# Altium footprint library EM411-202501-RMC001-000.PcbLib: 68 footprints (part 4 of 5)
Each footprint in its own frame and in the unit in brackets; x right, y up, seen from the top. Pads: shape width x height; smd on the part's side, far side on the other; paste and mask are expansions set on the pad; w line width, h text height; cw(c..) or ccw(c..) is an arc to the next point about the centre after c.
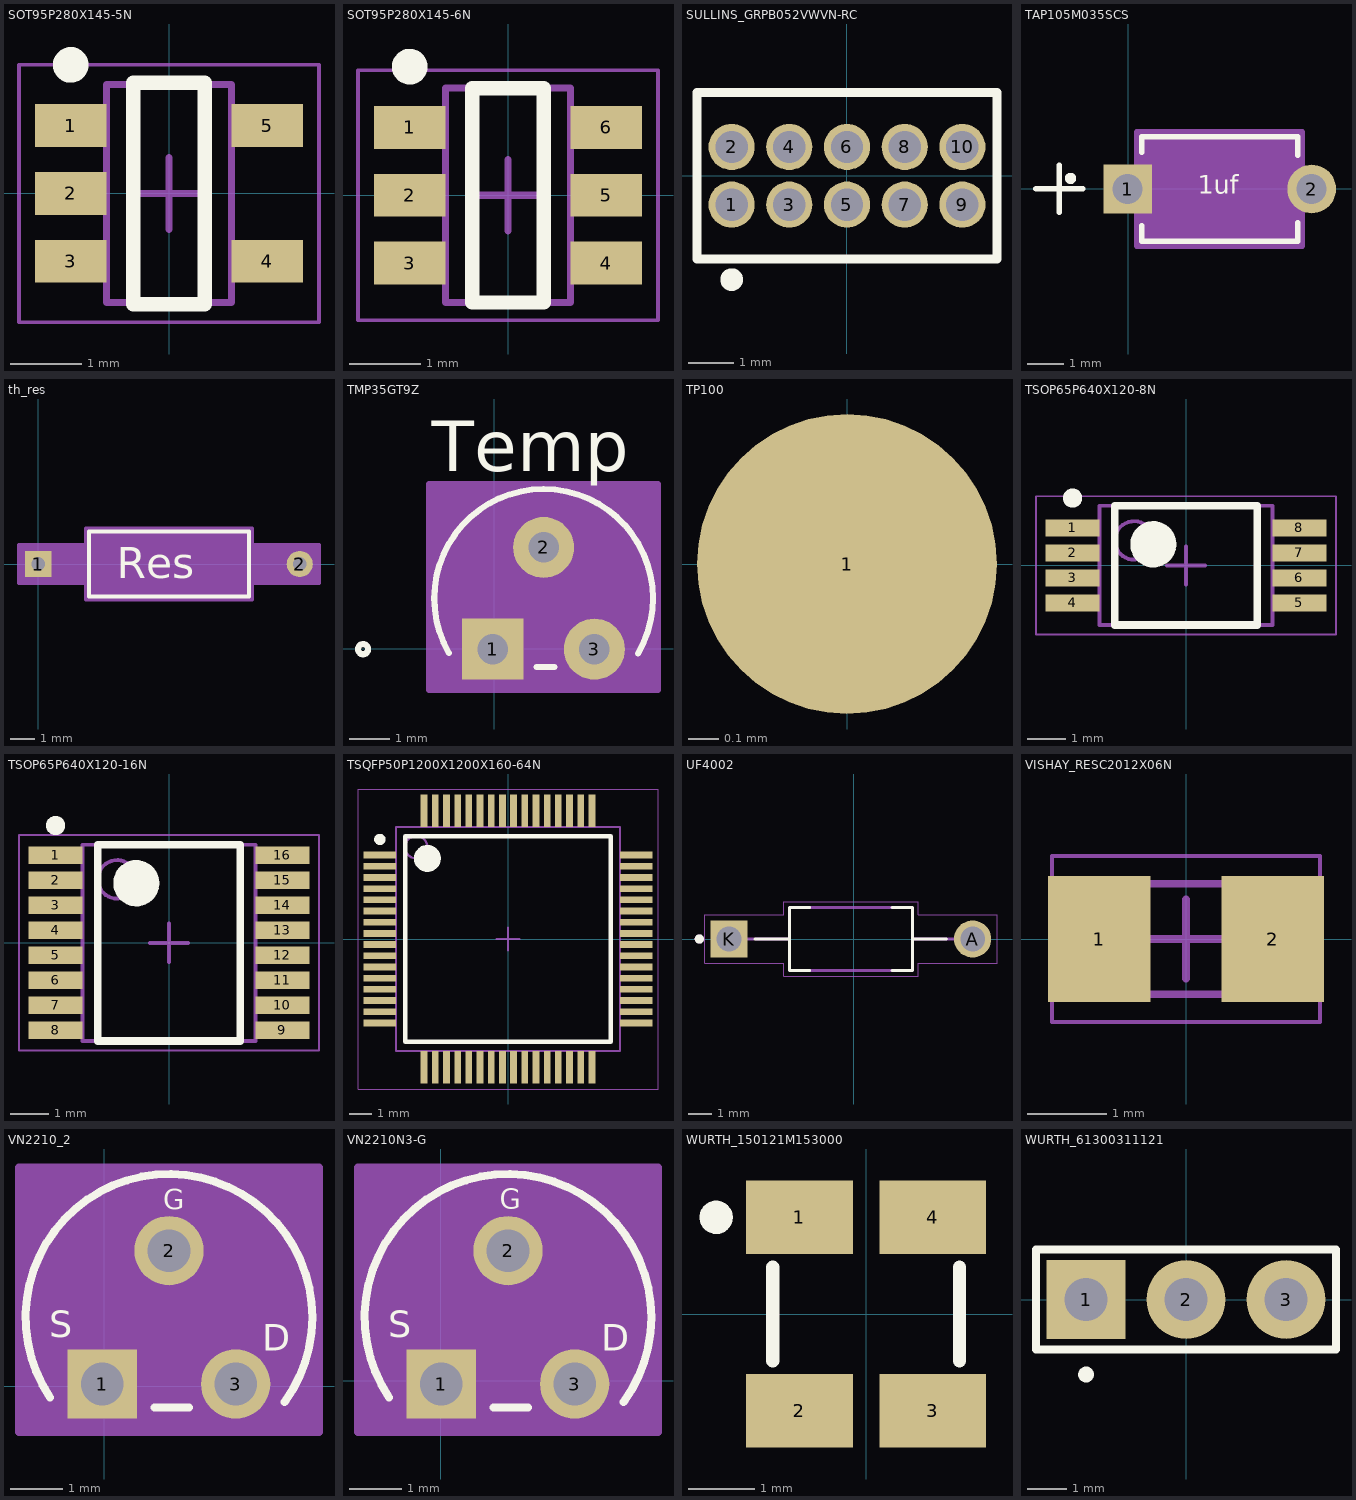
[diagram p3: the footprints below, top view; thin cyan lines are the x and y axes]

## SOT95P280X145-5N [mm] "SOT23, 5-Leads, Body 2.90x2.80mm, Pitch 0.95mm, IPC Medium Density"
height 1.45
pads (5):
  rect 1x0.6 smd: 1(-1.375,0.95) 2(-1.375,0) 3(-1.375,-0.95) 4(1.375,-0.95) 5(1.375,0.95)
Top Overlay:
  circle w0.25: c-1.375,1.8 r0.125
  lines w0.2: -0.5,-1.55 0.5,-1.55 0.5,1.55 -0.5,1.55 -0.5,-1.55
Top Courtyard:
  lines w0.05: -2.1,-1.8 -2.1,1.8 2.1,1.8 2.1,-1.8 -2.1,-1.8
  lines w0.1: -0.5,0 0.5,0 ; 0,-0.5 0,0.5
Mechanical 13:
  lines w0.1: -0.875,-1.525 -0.875,1.525 0.875,1.525 0.875,-1.525 -0.875,-1.525
3D body "SOT95P280X145-5N.step": height 1.45, standoff 0, extent -1.5,-1.525 1.5,1.525

## SOT95P280X145-6N [mm] "SOT23, 6-Leads, Body 2.90x2.80mm, Pitch 0.95mm, IPC Medium Density"
height 1.45
pads (6):
  rect 1x0.6 smd: 1(-1.375,0.95) 2(-1.375,0) 3(-1.375,-0.95) 4(1.375,-0.95) 5(1.375,0) 6(1.375,0.95)
Top Overlay:
  circle w0.25: c-1.375,1.8 r0.125
  lines w0.2: -0.5,-1.5 0.5,-1.5 0.5,1.5 -0.5,1.5 -0.5,-1.5
Top Courtyard:
  lines w0.05: -2.1,-1.75 -2.1,1.75 2.1,1.75 2.1,-1.75 -2.1,-1.75
  lines w0.1: -0.5,0 0.5,0 ; 0,-0.5 0,0.5
Mechanical 13:
  lines w0.1: -0.875,-1.5 -0.875,1.5 0.875,1.5 0.875,-1.5 -0.875,-1.5
3D body "SOT95P280X145-6N.step": height 1.45, standoff 0, extent -1.5,-1.5 1.5,1.5

## SULLINS_GRPB052VWVN-RC [mil] "CONN HEADER VERT 10POS 1.27MM"
height 157.48
pads (10):
  round 40 hole 28: 1(-100,-25) 2(-100,25) 3(-50,-25) 4(-50,25) 5(0,-25) 6(0,25) 7(50,-25) 8(50,25) 9(100,-25) 10(100,25)
Top Overlay:
  circle w9.84: c-100,-90 r4.92
  lines w7.87: -130,-72 130,-72 130,72 -130,72 -130,-72
3D body "FTS-105-01-L-D.stp": height 154, standoff -90, extent -125,-67.5 125,67.5

## TAP105M035SCS [mil]
pads (2):
  rect 52x52 hole 32 paste-99999 mask+0: 1(-0.55,-0.19)
  round 52 hole 32 paste-99999 mask+0: 2(196.3,-0.19)
Top Overlay:
  circle w6: c-61.57,11.17 r3
  lines w6: -98.5,0 -48.5,0 ; -73.5,-25 -73.5,25 ; 14.38,-39.29 14.38,-56.19 181.38,-56.19 181.38,-36.33 ; 14.38,38.91 14.38,55.81 181.38,55.81 181.38,35.95
  text "1uf" at 74.45,-5.19 h20
Mechanical 13:
  circle w1: c39.38,-0.19 r3
  lines w1: -98.5,0 -48.5,0 ; -73.5,-25 -73.5,25 ; 19.38,-51.19 176.38,-51.19 176.38,50.81 19.38,50.81 19.38,-51.19
  text "C" at -39.62,-25.19 h50
Mechanical 15:
  region: 186.38,-61.19 9.38,-61.19 9.38,60.81 186.38,60.81
  lines w6: 9.38,-61.19 9.38,60.81 186.38,60.81 186.38,-61.19 9.38,-61.19
3D body "CAP_K-SERIES_15-H5_VIS.step": height 307.99, standoff -52.01, extent -20.96,-47.16 219.87,54.81

## th_res [mil]
pads (2):
  rect 42x42 hole 22 paste-99999 mask+0: 1(0,0)
  round 42 hole 22 paste-99999 mask+0: 2(421.26,0)
Top Overlay:
  lines w6: 81.63,-52.5 339.63,-52.5 339.63,52.5 81.63,52.5 81.63,-52.5
  text "Res" at 126.49,-23.18 h50
Mechanical 13:
  lines w1: 0,0 86.63,0 ; 334.63,0 421.26,0 ; 86.63,-47.5 334.63,-47.5 334.63,47.5 86.63,47.5 86.63,-47.5
Mechanical 15:
  region: 76.63,-31 -31,-31 -31,31 76.63,31 76.63,57.5 344.63,57.5 344.63,31 452.26,31 452.26,-31 344.63,-31 344.63,-57.5 76.63,-57.5
  lines w6: -31,-31 -31,31 76.63,31 76.63,57.5 344.63,57.5 344.63,31 452.26,31 452.26,-31 344.63,-31 344.63,-57.5 76.63,-57.5 76.63,-31 -31,-31
3D body "RES_CFR25_6P3X2P4_YAG.step": height 94.98, standoff -100, extent -5.98,-47.15 427.24,47.15

## TMP35GT9Z [mil]
pads (3):
  rect 60x60 hole 30 paste-99999 mask+0: 1(-1.25,-0.24)
  round 60 hole 30 paste-99999 mask+0: 2(48.75,99.76) 3(98.75,-0.24)
Top Overlay:
  circle w6: c-128.75,-0.24 r5
  lines w6: -44.35,-3.99 cw(c48.75,49.76) 156.25,49.76 cw(c48.75,49.76) 141.65,-4.32 ; 41.85,-17.74 59.36,-17.74
  text "Temp" at -61.25,174.76 h50
Mechanical 13:
  circle w1: c-43.75,-0.24 r5
  lines w1: -32.49,-12.74 cw(c48.75,49.76) 129.99,-12.74 -32.49,-12.74
  lines w6: -11.25,-0.24 8.75,-0.24 ; -1.25,-10.24 -1.25,9.76
Mechanical 15:
  region: 161.25,-40.24 -63.75,-40.24 -63.75,162.26 161.25,162.26
  lines w6: -63.75,-40.24 -63.75,162.26 161.25,162.26 161.25,-40.24 -63.75,-40.24
3D body "T_3_ADI.step": height 290, standoff -100, extent -53.64,-10.24 151.13,151.79

## TP100 [mm] "Surface Mount Test Point"
height 7.4
pads (1):
  round 1 smd: 1(0,0)

## TSOP65P640X120-8N [mm] "TSOP, 8-Leads, Body 3.00x4.40mm, Pitch 0.65mm, IPC Medium Density"
height 1.2
pads (8):
  rect 1.4x0.45 smd: 1(-2.95,0.975) 2(-2.95,0.325) 3(-2.95,-0.325) 4(-2.95,-0.975) 5(2.95,-0.975) 6(2.95,-0.325) 7(2.95,0.325) 8(2.95,0.975)
Top Overlay:
  circle w0.6: c-0.85,0.55 r0.3
  circle w0.25: c-2.95,1.75 r0.125
  lines w0.2: -1.85,-1.55 1.85,-1.55 1.85,1.55 -1.85,1.55 -1.85,-1.55
Top Courtyard:
  lines w0.05: -3.9,-1.8 3.9,-1.8 3.9,1.8 -3.9,1.8 -3.9,-1.8
  lines w0.1: -0.5,0 0.5,0 ; 0,-0.5 0,0.5
Mechanical 13:
  circle w0.1: c-1.35,0.65 r0.5
  lines w0.1: -2.25,-1.55 2.25,-1.55 2.25,1.55 -2.25,1.55 -2.25,-1.55
3D body "TSOP65P640X120-8N.step": height 1.2, standoff 0, extent -3.2,-1.55 3.2,1.55

## TSOP65P640X120-16N [mm] "TSOP, 16-Leads, Body 5.00x4.40mm, Pitch 0.65mm, IPC Medium Density"
height 1.2
pads (16):
  rect 1.4x0.45 smd: 1(-2.95,2.275) 2(-2.95,1.625) 3(-2.95,0.975) 4(-2.95,0.325) 5(-2.95,-0.325) 6(-2.95,-0.975) 7(-2.95,-1.625) 8(-2.95,-2.275) 9(2.95,-2.275) 10(2.95,-1.625) 11(2.95,-0.975) 12(2.95,-0.325) 13(2.95,0.325) 14(2.95,0.975) 15(2.95,1.625) 16(2.95,2.275)
Top Overlay:
  circle w0.6: c-0.85,1.55 r0.3
  circle w0.25: c-2.95,3.05 r0.125
  lines w0.2: -1.85,-2.55 1.85,-2.55 1.85,2.55 -1.85,2.55 -1.85,-2.55
Top Courtyard:
  lines w0.05: -3.9,-2.8 3.9,-2.8 3.9,2.8 -3.9,2.8 -3.9,-2.8
  lines w0.1: -0.5,0 0.5,0 ; 0,-0.5 0,0.5
Mechanical 13:
  circle w0.1: c-1.35,1.65 r0.5
  lines w0.1: -2.25,-2.55 2.25,-2.55 2.25,2.55 -2.25,2.55 -2.25,-2.55
3D body "TSOP65P640X120-16N.step": height 1.2, standoff 0, extent -3.2,-2.55 3.2,2.55

## TSQFP50P1200X1200X160-64N [mm] "TSQFP, 64-Leads, Body 10.00x10.00mm, Pitch 0.50mm, IPC Medium Density"
height 1.6
pads (64):
  rect 1.45x0.3 smd: 1(-5.725,3.75) 2(-5.725,3.25) 3(-5.725,2.75) 4(-5.725,2.25) 5(-5.725,1.75) 6(-5.725,1.25) 7(-5.725,0.75) 8(-5.725,0.25) 9(-5.725,-0.25) 10(-5.725,-0.75) 11(-5.725,-1.25) 12(-5.725,-1.75) 13(-5.725,-2.25) 14(-5.725,-2.75) 15(-5.725,-3.25) 16(-5.725,-3.75) 33(5.725,-3.75) 34(5.725,-3.25) 35(5.725,-2.75) 36(5.725,-2.25) 37(5.725,-1.75) 38(5.725,-1.25) 39(5.725,-0.75) 40(5.725,-0.25) 41(5.725,0.25) 42(5.725,0.75) 43(5.725,1.25) 44(5.725,1.75) 45(5.725,2.25) 46(5.725,2.75) 47(5.725,3.25) 48(5.725,3.75)
  rect 0.3x1.45 smd: 17(-3.75,-5.725) 18(-3.25,-5.725) 19(-2.75,-5.725) 20(-2.25,-5.725) 21(-1.75,-5.725) 22(-1.25,-5.725) 23(-0.75,-5.725) 24(-0.25,-5.725) 25(0.25,-5.725) 26(0.75,-5.725) 27(1.25,-5.725) 28(1.75,-5.725) 29(2.25,-5.725) 30(2.75,-5.725) 31(3.25,-5.725) 32(3.75,-5.725) 49(3.75,5.725) 50(3.25,5.725) 51(2.75,5.725) 52(2.25,5.725) 53(1.75,5.725) 54(1.25,5.725) 55(0.75,5.725) 56(0.25,5.725) 57(-0.25,5.725) 58(-0.75,5.725) 59(-1.25,5.725) 60(-1.75,5.725) 61(-2.25,5.725) 62(-2.75,5.725) 63(-3.25,5.725) 64(-3.75,5.725)
Top Overlay:
  circle w0.25: c-5.725,4.45 r0.125
  circle w0.6: c-3.6,3.6 r0.3
  lines w0.2: -4.6,-4.6 -4.6,4.6 4.6,4.6 4.6,-4.6 -4.6,-4.6
Top Courtyard:
  lines w0.05: -6.7,-6.7 -6.7,6.7 6.7,6.7 6.7,-6.7 -6.7,-6.7
  lines w0.1: -0.5,0 0.5,0 ; 0,-0.5 0,0.5
Mechanical 13:
  circle w0.1: c-4.1,4.1 r0.5
  lines w0.1: -5,-5 -5,5 5,5 5,-5 -5,-5
3D body "TSQFP50P1200X1200X160-64N.step": height 1.6, standoff 0, extent -6,-6 6,6

## UF4002 [mm] "Diode 100 V 1A Through Hole DO-41"
pads (2):
  round 1.61 hole 1.07: A(5.148,0)
  rect 1.61x1.61 hole 1.07: K(-5.402,0)
Top Overlay:
  circle w0.2: c-6.692,0 r0.1
  lines w0.127: -4.277,0 -2.827,0 ; -1.907,-1.36 -2.792,-1.36 -2.792,1.36 -1.907,1.36 ; 1.653,-1.36 2.538,-1.36 2.538,0 ; 1.653,1.36 2.538,1.36 2.538,0 ; 4.023,0 2.538,0
Mechanical 13:
  circle w0.2: c-6.692,0 r0.1
  lines w0.127: -4.597,0 -2.792,0 ; 4.343,0 2.538,0 ; -2.792,0 -2.792,1.36 2.538,1.36 2.538,0 ; -2.792,0 -2.792,-1.36 2.538,-1.36 2.538,0
Mechanical 15:
  lines w0.05: -6.457,-1.055 -6.457,1.055 -3.042,1.055 -3.042,1.61 2.788,1.61 2.788,1.055 6.203,1.055 6.203,-1.055 2.788,-1.055 2.788,-1.61 -3.042,-1.61 -3.042,-1.055 -6.457,-1.055
3D body "UF4002.step": height 2.71, standoff -21.76, extent -5.827,-1.36 5.319,1.36

## VISHAY_RESC2012X06N [mm] "Chip Resistor, 2-Leads, Body 2.00x1.25mm, IPC Medium Density"
height 0.6
pads (2):
  rect 1.3x1.6 smd: 1(-1.1,0) 2(1.1,0)
Top Courtyard:
  lines w0.05: -1.7,-1.05 1.7,-1.05 1.7,1.05 -1.7,1.05 -1.7,-1.05
  lines w0.1: -0.5,0 0.5,0 ; 0,-0.5 0,0.5
Mechanical 13:
  lines w0.1: -1.075,-0.7 1.075,-0.7 1.075,0.7 -1.075,0.7 -1.075,-0.7
3D body "VISHAY_RESC2012X06N.step": height 0.6, standoff 0, extent -1.075,-0.7 1.075,0.7

## VN2210_2 [mil]
pads (3):
  rect 52x52 hole 32 paste-99999 mask+0: 1(-1.3,1.52)
  round 52 hole 32 paste-99999 mask+0: 2(48.7,101.52) 3(98.7,1.52)
Top Overlay:
  lines w6: -40.4,-8.63 cw(c48.7,51.52) 156.2,51.52 cw(c48.7,51.52) 135.35,-12.11 ; 37.8,-15.98 63.73,-15.98
  text "S" at -41.3,36.52 h20
  text "G" at 44.37,132.6 h15
  text "D" at 118.7,26.52 h20
Mechanical 13:
  circle w1: c-43.8,1.52 r5
  lines w1: -32.54,-10.98 cw(c48.7,51.52) 129.94,-10.98 -32.54,-10.98
  lines w6: -11.3,1.52 8.7,1.52 ; -1.3,-8.48 -1.3,11.52
Mechanical 15:
  region: 161.2,-34.48 -63.8,-34.48 -63.8,164.02 161.2,164.02
  lines w6: -63.8,-34.48 -63.8,164.02 161.2,164.02 161.2,-34.48 -63.8,-34.48
3D body "TO-92_FAS.step": height 290, standoff -107.99, extent -53.69,-9.47 151.08,153.55

## VN2210N3-G [mil]
pads (3):
  rect 52x52 hole 32 paste-99999 mask+0: 1(0.31,-2.57)
  round 52 hole 32 paste-99999 mask+0: 2(50.31,97.43) 3(100.31,-2.57)
Top Overlay:
  lines w6: -38.79,-12.72 cw(c50.31,47.43) 157.81,47.43 cw(c50.31,47.43) 136.96,-16.2 ; 39.41,-20.07 65.34,-20.07
  text "D" at 120.31,22.43 h20
  text "G" at 44.1,128.87 h15
  text "S" at -39.69,32.43 h20
Mechanical 13:
  circle w1: c-42.19,-2.57 r5
  lines w1: -30.93,-15.07 cw(c50.31,47.43) 131.55,-15.07 -30.93,-15.07
  lines w6: -9.69,-2.57 10.31,-2.57 ; 0.31,-12.57 0.31,7.43
Mechanical 15:
  region: 162.81,-38.57 -62.19,-38.57 -62.19,159.93 162.81,159.93
  lines w6: -62.19,-38.57 162.81,-38.57 162.81,159.93 -62.19,159.93 -62.19,-38.57
3D body "TO-92_FAS.step": height 290, standoff -107.99, extent -52.08,-13.56 152.7,149.47

## WURTH_150121M153000 [mm]
height 6.5
pads (4):
  rect 1.6x1.1 smd: 1(-1,1.45) 2(-1,-1.45) 3(1,-1.45) 4(1,1.45)
Top Overlay:
  circle w0.25: c-2.25,1.45 r0.125
  lines w0.2: -1.4,-0.7 -1.4,0.7 ; 1.4,-0.7 1.4,0.7
3D body "150121M153000.stp": height 1.08, standoff -0.02, extent -1.35,-1.6 1.35,1.6

## WURTH_61300311121 [mm]
height 7.4
pads (3):
  rect 2x2 hole 1.1: 1(-2.54,0)
  round 2 hole 1.1: 2(0,0) 3(2.54,0)
Top Overlay:
  circle w0.2: c-2.54,-1.905 r0.1
  lines w0.2: -3.81,-1.27 -3.81,1.27 3.81,1.27 3.81,-1.27 -3.81,-1.27
3D body "TSW-103-07-G-S.stp": height 8.41, standoff -2.51, extent -3.937,-1.27 3.81,1.27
